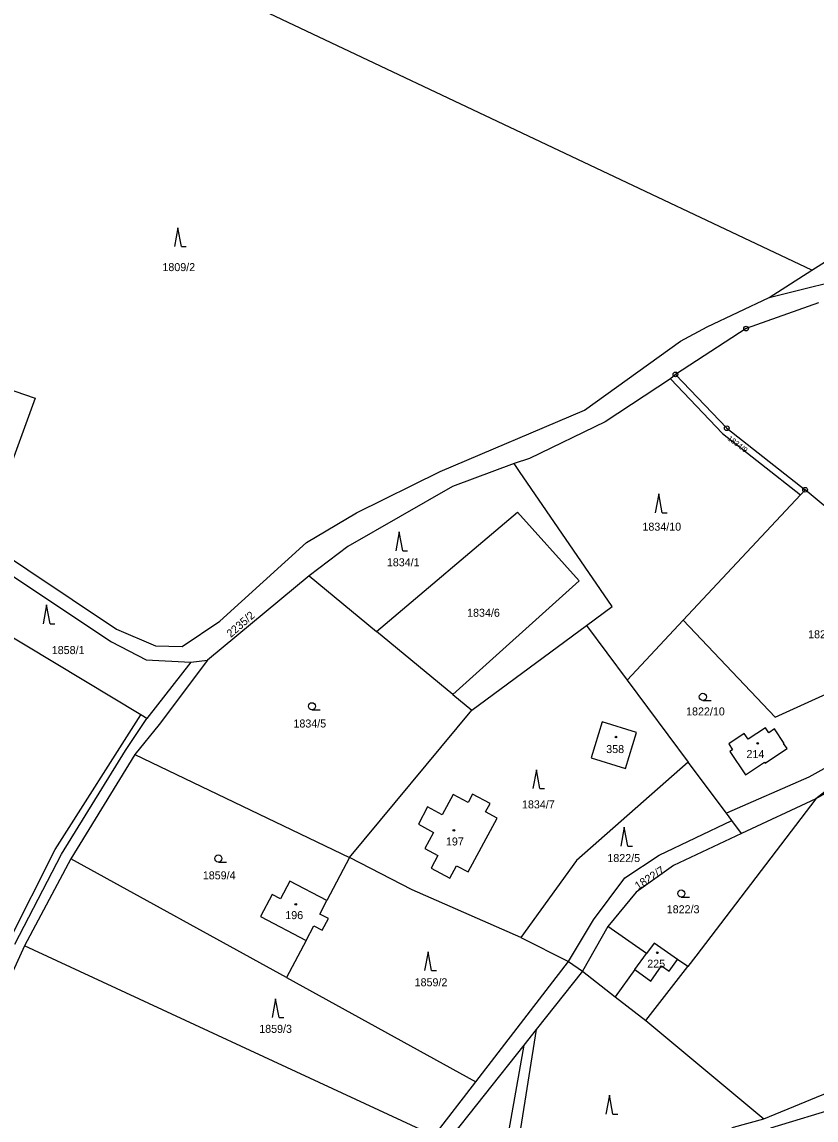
# Model space of a CAD drawing. Extents: x -725728 to -720881, y -1068679 to -1063504.
# Drawn here: x -723092.7 to -722924.1, y -1067751.9 to -1067518.7 of the extents above; entities that cross this region are included whole.
import ezdxf

# ---------------------------------------------------------------- set-up
doc = ezdxf.new("R2010")
doc.units = 0
for name, color, linetype in [('Hranice parcel', 7, 'Continuous'), ('Parcelní čísla', 7, 'Continuous'), ('Vnitřní kresba', 7, 'Continuous'), ('Značky bodu BP', 7, 'Continuous'), ('Značky budov', 7, 'Continuous'), ('Značky kultur', 7, 'Continuous')]:
    doc.layers.add(name, color=color, linetype=linetype)

msp = doc.modelspace()

# ---------------------------------------------------------------- linework, layer by layer
at = {"layer": 'Hranice parcel'}
for p, q in [((-722934.08, -1067577.18), (-722924.95, -1067571.4)), ((-722953.94, -1067593.51), (-722955.02, -1067594.46)), ((-722927.39, -1067619.1), (-722952.28, -1067645.69)), ((-722926.4, -1067618.03), (-722927.39, -1067619.1)), ((-722909.36, -1067632.27), (-722926.4, -1067618.03)), ((-723031.73, -1067636.3), (-723053.31, -1067654.18)), ((-723031.73, -1067636.3), (-723017.41, -1067648.14)), ((-723067.52, -1067665.83), (-723102.1, -1067644.99)), ((-723067.52, -1067665.83), (-723102.1, -1067644.99)), ((-722997.2, -1067664.84), (-722972.83, -1067646.88)), ((-722972.83, -1067646.88), (-722964.23, -1067658.47)), ((-722952.28, -1067645.69), (-722964.23, -1067658.47)), ((-723001.23, -1067661.51), (-723017.41, -1067648.14)), ((-723056.89, -1067654.65), (-723053.31, -1067654.18)), ((-723056.89, -1067654.65), (-723066.2, -1067666.62)), ((-722964.23, -1067658.47), (-722951.25, -1067675.84)), ((-723001.23, -1067661.51), (-722997.2, -1067664.84)), ((-723066.2, -1067666.62), (-723067.52, -1067665.83)), ((-723066.2, -1067666.62), (-723067.52, -1067665.83)), ((-723023.19, -1067696.15), (-722997.2, -1067664.84)), ((-723070.73, -1067673.42), (-723066.2, -1067666.62)), ((-723070.73, -1067673.42), (-723066.2, -1067666.62)), ((-723084.33, -1067695.39), (-723070.73, -1067673.42)), ((-723084.33, -1067695.39), (-723070.73, -1067673.42)), ((-723068.75, -1067674.23), (-723082.34, -1067696.39)), ((-723068.75, -1067674.23), (-723023.19, -1067696.15)), ((-722943.13, -1067686.7), (-722951.25, -1067675.84)), ((-722924.1, -1067683.64), (-722939.89, -1067691.04)), ((-722941.94, -1067688.29), (-722943.13, -1067686.7)), ((-722939.89, -1067691.04), (-722941.94, -1067688.29)), ((-723094.26, -1067714.56), (-723084.33, -1067695.39)), ((-723094.26, -1067714.56), (-723084.33, -1067695.39)), ((-723082.34, -1067696.39), (-723092.23, -1067714.85)), ((-723036.54, -1067721.62), (-723082.34, -1067696.39)), ((-723023.19, -1067696.15), (-723027.96, -1067705.26)), ((-722968.31, -1067710.75), (-722973.7, -1067720.26)), ((-723005.19, -1067755.21), (-723092.23, -1067714.85)), ((-723032.41, -1067713.74), (-723036.54, -1067721.62)), ((-722986.79, -1067713.12), (-722976.65, -1067718.19)), ((-722996.36, -1067743.76), (-722976.65, -1067718.19)), ((-722976.65, -1067718.19), (-722973.7, -1067720.26)), ((-722960.25, -1067730.77), (-722951.34, -1067719.28)), ((-723036.54, -1067721.62), (-722996.36, -1067743.76)), ((-722973.7, -1067720.26), (-722983.56, -1067732.68)), ((-722960.25, -1067730.77), (-722935.2, -1067751.61)), ((-722983.56, -1067732.68), (-722986.15, -1067735.95)), ((-723005.19, -1067755.21), (-722996.36, -1067743.76)), ((-722935.2, -1067751.61), (-722918.04, -1067744.55)), ((-722910.09, -1067746.43), (-722933.76, -1067753.61))]:
    msp.add_line(p, q, dxfattribs=at)
for points in [[(-722924.95, -1067571.4), (-723093.85, -1067491.45), (-723139.95, -1067484.12)], [(-722924.95, -1067571.4), (-722884.6, -1067545.85), (-722866.81, -1067537.32)], [(-723220.03, -1067553.72), (-723089.93, -1067598.55), (-723100.95, -1067628.7)], [(-722934.08, -1067577.18), (-722893.13, -1067566.99), (-722875.52, -1067556.05)], [(-723100.95, -1067628.7), (-723072.64, -1067647.6), (-723064.41, -1067651.13), (-723058.72, -1067651.33), (-723050.68, -1067645.96), (-723032.31, -1067629.23), (-723021.66, -1067622.95), (-723003.89, -1067614.12), (-722973.3, -1067601.12), (-722952.86, -1067586.47), (-722947.2, -1067583.41), (-722934.08, -1067577.18)], [(-722923.58, -1067578.31), (-722938.95, -1067583.79), (-722953.94, -1067593.51)], [(-722953.94, -1067593.51), (-722943.05, -1067604.94), (-722926.4, -1067618.03)], [(-722955.02, -1067594.46), (-722968.85, -1067603.57), (-722984.95, -1067611.35), (-722988.23, -1067612.42)], [(-722955.02, -1067594.46), (-722943.95, -1067606.08), (-722927.39, -1067619.1)], [(-722988.23, -1067612.42), (-723001.27, -1067617.32), (-723023.5, -1067630.06), (-723031.73, -1067636.3)], [(-722972.83, -1067646.88), (-722967.37, -1067642.84), (-722987.05, -1067614.14), (-722988.23, -1067612.42)], [(-722857.97, -1067620.36), (-722887.42, -1067653.51), (-722901.58, -1067667.57), (-722907.89, -1067673.55), (-722914.09, -1067677.87), (-722924.1, -1067683.64)], [(-723017.41, -1067648.14), (-722987.52, -1067622.81), (-722974.41, -1067637.38), (-723001.23, -1067661.51)], [(-723102.1, -1067644.99), (-723122.43, -1067627.57), (-723102.63, -1067631.15), (-723073.72, -1067650.28), (-723066.37, -1067654.11), (-723056.89, -1067654.65)], [(-722952.28, -1067645.69), (-722932.79, -1067666.28), (-722912.7, -1067657.17), (-722906.54, -1067667.07)], [(-722887.95, -1067650.64), (-722909.33, -1067672.11), (-722924.1, -1067683.64)], [(-723053.31, -1067654.18), (-723063.58, -1067667.87), (-723068.75, -1067674.23)], [(-723040.57, -1068018.44), (-723041.45, -1068020.15), (-723053.84, -1068009.4), (-723063.01, -1067989.69), (-723068.96, -1067963.47), (-723082.51, -1067937.46), (-723117.57, -1067885.77), (-723133.55, -1067852.16), (-723146.34, -1067824.42), (-723143.95, -1067807.38), (-723131.43, -1067783.07), (-723114.25, -1067755.83), (-723095.64, -1067714.22), (-723085.72, -1067694.44), (-723067.52, -1067665.83)], [(-722969.52, -1067667.31), (-722971.86, -1067674.95), (-722964.59, -1067677.19)], [(-722964.59, -1067677.19), (-722962.24, -1067669.54), (-722969.52, -1067667.31)], [(-722906.54, -1067667.07), (-722911.73, -1067671.37), (-722925.59, -1067679.04), (-722943.13, -1067686.7)], [(-722930.25, -1067672.98), (-722930.97, -1067671.92), (-722930.85, -1067671.9), (-722932.92, -1067668.79), (-722934.15, -1067669.61), (-722934.84, -1067668.57), (-722938.49, -1067671), (-722939.32, -1067669.76), (-722942.64, -1067671.97), (-722941.81, -1067673.22), (-722942.43, -1067673.63), (-722939.08, -1067678.55), (-722935.06, -1067675.9), (-722934.92, -1067676.11), (-722931.4, -1067673.75), (-722930.25, -1067672.98)], [(-722951.25, -1067675.84), (-722974.95, -1067696.75), (-722986.79, -1067713.12)], [(-722991.83, -1067687.74), (-722994.27, -1067686.43), (-722993.33, -1067684.68), (-722997.04, -1067682.67), (-722997.98, -1067684.43), (-723001.15, -1067682.73), (-723003.47, -1067687.04), (-723006.58, -1067685.37), (-723008.55, -1067689.05), (-723005.33, -1067690.78), (-723007.18, -1067694.23), (-723004.42, -1067695.72), (-723005.84, -1067698.36), (-723001.84, -1067700.51), (-723000.42, -1067697.87), (-722997.98, -1067699.18), (-722991.83, -1067687.74)], [(-722924.1, -1067683.64), (-722949.62, -1067717.07), (-722951.34, -1067719.28)], [(-722976.65, -1067718.19), (-722971.38, -1067709.39), (-722964.71, -1067700.41), (-722957.43, -1067695.64), (-722941.94, -1067688.29)], [(-722939.89, -1067691.04), (-722954.36, -1067697.82), (-722962.32, -1067703.47), (-722968.31, -1067710.75)], [(-722986.79, -1067713.12), (-723009.84, -1067702.99), (-723023.19, -1067696.15)], [(-723027.96, -1067705.26), (-723035.86, -1067701.12), (-723037.85, -1067704.92), (-723039.62, -1067704), (-723042.07, -1067708.68), (-723032.41, -1067713.74)], [(-723032.41, -1067713.74), (-723030.77, -1067710.62), (-723028.98, -1067711.56), (-723027.67, -1067709.06), (-723029.46, -1067708.12), (-723027.96, -1067705.26)], [(-722951.34, -1067719.28), (-722953.51, -1067717.76), (-722958.47, -1067714.29), (-722960.08, -1067716.52), (-722968.31, -1067710.75)], [(-723092.23, -1067714.85), (-723110.84, -1067755.63), (-723126.94, -1067781.78), (-723139.93, -1067807.34), (-723143.18, -1067823.44), (-723131.07, -1067851.95), (-723114.38, -1067885.05), (-723080.12, -1067934.54), (-723068.54, -1067955.25)], [(-722973.7, -1067720.26), (-722966.73, -1067725.7), (-722960.25, -1067730.77)], [(-722983.56, -1067732.68), (-722988.61, -1067764.89), (-722986.79, -1067785.49)], [(-722986.15, -1067735.95), (-723003.03, -1067757.23), (-723043.34, -1067823.44), (-723053.29, -1067834.22), (-723059.1, -1067846.51), (-723061.91, -1067861.04), (-723062.69, -1067910.96)], [(-722986.15, -1067735.95), (-722991.43, -1067765.89), (-722990.83, -1067789.1)], [(-722986.79, -1067785.49), (-722966.03, -1067766.96), (-722941.65, -1067753.36), (-722935.2, -1067751.61)]]:
    msp.add_lwpolyline(points, dxfattribs=at)
at = {"layer": 'Vnitřní kresba'}
for p, q in [((-722962.56, -1067719.94), (-722960.08, -1067716.52)), ((-722959.15, -1067722.35), (-722956.9, -1067719.14)), ((-722956.9, -1067719.14), (-722955.27, -1067720.28)), ((-722955.27, -1067720.28), (-722953.51, -1067717.76)), ((-722962.56, -1067719.94), (-722966.73, -1067725.7)), ((-722962.56, -1067719.94), (-722959.15, -1067722.35))]:
    msp.add_line(p, q, dxfattribs=at)
at = {"layer": 'Značky bodu BP'}
for centre, radius in [((-722938.95, -1067583.79), 0.5), ((-722938.95, -1067583.79), 0.0303), ((-722953.94, -1067593.51), 0.5), ((-722953.94, -1067593.51), 0.0303), ((-722943.05, -1067604.94), 0.5), ((-722943.05, -1067604.94), 0.0303), ((-722926.4, -1067618.03), 0.5), ((-722926.4, -1067618.03), 0.0303)]:
    msp.add_circle(centre, radius, dxfattribs=at)
at = {"layer": 'Značky budov'}
for centre in [(-722966.59, -1067670.53), (-722936.48, -1067671.89), (-723001, -1067690.35), (-723034.59, -1067706.05), (-722957.81, -1067716.36)]:
    msp.add_circle(centre, 0.175, dxfattribs=at)
at = {"layer": 'Značky kultur'}
for p, q in [((-723059.6, -1067562.37), (-723060.35, -1067566.37)), ((-723058.85, -1067566.37), (-723059.6, -1067562.37)), ((-723058.85, -1067566.37), (-723057.85, -1067566.37)), ((-722957.49, -1067618.89), (-722958.24, -1067622.89)), ((-722956.74, -1067622.89), (-722957.49, -1067618.89)), ((-722956.74, -1067622.89), (-722955.74, -1067622.89)), ((-723012.62, -1067626.98), (-723013.37, -1067630.98)), ((-723011.87, -1067630.98), (-723012.62, -1067626.98)), ((-723011.87, -1067630.98), (-723010.87, -1067630.98)), ((-723087.51, -1067642.46), (-723088.26, -1067646.46)), ((-723086.76, -1067646.46), (-723087.51, -1067642.46)), ((-723086.76, -1067646.46), (-723085.76, -1067646.46)), ((-722948.13, -1067662.75), (-722946.38, -1067662.75)), ((-723031.15, -1067664.74), (-723029.4, -1067664.74)), ((-722983.48, -1067677.48), (-722984.23, -1067681.48)), ((-722982.73, -1067681.48), (-722983.48, -1067677.48)), ((-722982.73, -1067681.48), (-722981.73, -1067681.48)), ((-722964.83, -1067689.69), (-722965.58, -1067693.69)), ((-722964.08, -1067693.69), (-722964.83, -1067689.69)), ((-722964.08, -1067693.69), (-722963.08, -1067693.69)), ((-723051.03, -1067697.08), (-723049.28, -1067697.08)), ((-722952.71, -1067704.52), (-722950.96, -1067704.52)), ((-723006.48, -1067716.14), (-723007.23, -1067720.14)), ((-723005.73, -1067720.14), (-723006.48, -1067716.14)), ((-723005.73, -1067720.14), (-723004.73, -1067720.14)), ((-723038.87, -1067726.13), (-723039.62, -1067730.13)), ((-723038.12, -1067730.13), (-723038.87, -1067726.13)), ((-723038.12, -1067730.13), (-723037.12, -1067730.13)), ((-722967.97, -1067746.6), (-722968.72, -1067750.6)), ((-722967.22, -1067750.6), (-722967.97, -1067746.6)), ((-722967.22, -1067750.6), (-722966.22, -1067750.6))]:
    msp.add_line(p, q, dxfattribs=at)
for centre in [(-722948.13, -1067662), (-723031.15, -1067663.99), (-723051.03, -1067696.33), (-722952.71, -1067703.77)]:
    msp.add_circle(centre, 0.75, dxfattribs=at)

# ---------------------------------------------------------------- texts
at = {"layer": 'Parcelní čísla'}
for s, p in [('1809/2', (-723062.91, -1067571.58)), ('1834/10', (-722960.96, -1067626.71)), ('1834/1', (-723015.24, -1067634.27)), ('1834/6', (-722998.2, -1067644.99)), ('1822/4', (-722925.77, -1067649.56)), ('1858/1', (-723086.41, -1067652.92)), ('1822/10', (-722951.69, -1067665.95)), ('1834/5', (-723035.08, -1067668.51)), ('358', (-722968.65, -1067673.94)), ('214', (-722938.86, -1067675)), ('1834/7', (-722986.54, -1067685.69)), ('197', (-723002.69, -1067693.57)), ('1822/5', (-722968.41, -1067697.09)), ('1859/4', (-723054.33, -1067700.76)), ('196', (-723036.81, -1067709.21)), ('1822/3', (-722955.8, -1067707.96)), ('225', (-722959.94, -1067719.52)), ('1859/2', (-723009.34, -1067723.47)), ('1859/3', (-723042.35, -1067733.36))]:
    msp.add_text(s, height=1.7, dxfattribs=at).set_placement(p)
for s, height, rotation, p in [('1834/9', 1.14, 323, (-722943, -1067607.33)), ('2235/2', 1.7, 41, (-723048.38, -1067649.51)), ('1822/7', 1.7, 33, (-722961.9, -1067703.05))]:
    msp.add_text(s, height=height, rotation=rotation, dxfattribs=at).set_placement(p)

doc.saveas('drawing.dxf')
